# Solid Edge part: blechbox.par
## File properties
Author: Administrator
Template: Normal.par
Last saved by: Administrator
Revision: 1
Application: Solid Edge
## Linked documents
Blechbox.psm
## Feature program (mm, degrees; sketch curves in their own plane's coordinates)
part copy "unnamed PartCopy 1"
